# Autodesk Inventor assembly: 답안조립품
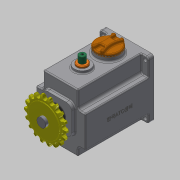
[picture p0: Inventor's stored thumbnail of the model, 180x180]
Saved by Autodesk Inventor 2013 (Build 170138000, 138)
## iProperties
Created: 2017-12
Part Number: 답안조립품
Document SubType Name: Assembly
Designer: Administrator
Mass: 2741.18 g
Surface Area: 2015.58 cm^2
Volume: 734.132 cm^3
Density: 3.7339 g/cm^3
Author: Administrator
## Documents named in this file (17)
- C:\Users\Administrator\Desktop\371208V1023\답안조립품.iam
- C:\Users\Administrator\Desktop\371208V1023\본체.ipt
- C:\Users\Administrator\Desktop\371208V1023\가변스프링.ipt
- C:\Users\Administrator\Desktop\371208V1023\멈춤나사 M3x8.ipt
- C:\Users\Administrator\Desktop\371208V1023\메인축.ipt
- C:\Users\Administrator\Desktop\371208V1023\베어링 608.ipt
- C:\Users\Administrator\Desktop\371208V1023\베어링 6003.ipt
- C:\Users\Administrator\Desktop\371208V1023\볼트 M4 x 10.ipt
- C:\Users\Administrator\Desktop\371208V1023\부시.ipt
- C:\Users\Administrator\Desktop\371208V1023\상부 캡.ipt
- C:\Users\Administrator\Desktop\371208V1023\서브축.ipt
- C:\Users\Administrator\Desktop\371208V1023\스프로킷.ipt
- C:\Users\Administrator\Desktop\371208V1023\슬라이더.ipt
- C:\Users\Administrator\Desktop\371208V1023\오일 실 8 22 7.ipt
- C:\Users\Administrator\Desktop\371208V1023\오일 실 17 32 8.ipt
- C:\Users\Administrator\Desktop\371208V1023\커버.ipt
- C:\Users\Administrator\Desktop\371208V1023\키 5 x 5 x 18.ipt
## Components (1 placed, 1 different names)
1. 가변스프링:1
